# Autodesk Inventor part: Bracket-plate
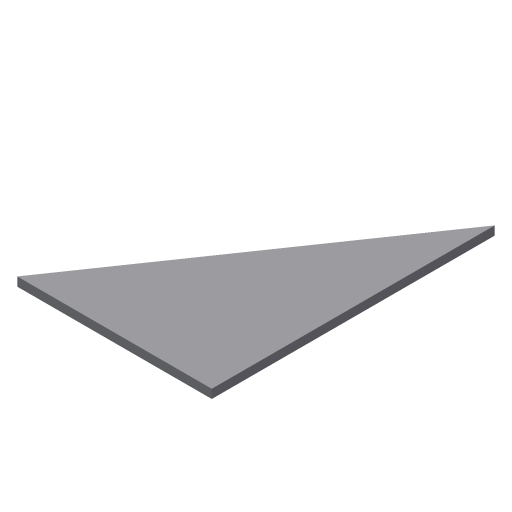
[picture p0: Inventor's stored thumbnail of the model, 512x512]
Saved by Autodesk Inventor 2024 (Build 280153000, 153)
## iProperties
Shininess: 64.0
Length Units: 11269
Angle Units: 11279
Time Units: 11290
Mass Units: 11283
Length Display Precision: 3
Angle Display Precision: 2
Compacted: True
Part Number: Bracket-plate
Document SubType Name: Modeling
Created: 2003-01
Designer: Owner
Density: 1 g/cm^3
Material: Generic
Appearance: Default
Density: 0.0
Volumn: 0.0
Area: 0.0
PropertySet Name: Model Information
Control State: 0
Master: False
Checked Out: False
Author: Owner
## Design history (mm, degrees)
sketch "Sketch1"
  geometry: L1 (-27.627, 0.004)-(-0.127, 0.004); L2 (-0.127, 0.004)-(-0.127, 40.004); L3 (-0.127, 40.004)-(-27.627, 0.004)
  constraints: 6 end point, 1 horizontal, 1 perpendicular
  dimensions: "d0" = 27.5 distance of L1.start L1.end; "d1" = 40 distance of L1.end L2.end
extrude "Extrusion1" new body sketch "Sketch1" distance "d2" = 1.25; taper "d3" = 0 deg
body "Solid1"
